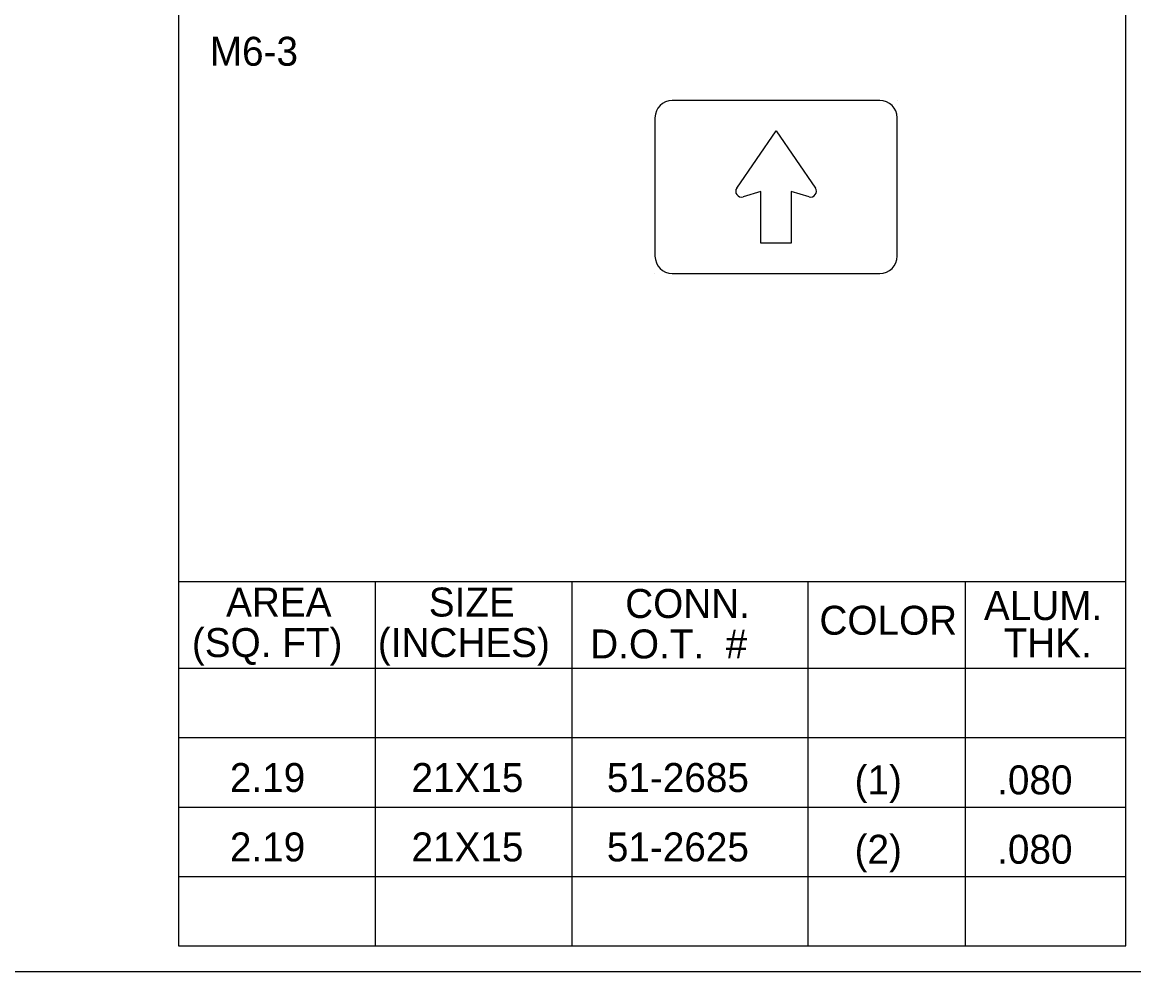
# Model space of a CAD drawing. Extents: x 0 to 2011, y -22 to 1183.
# Drawn here: x 616.3 to 739.2, y 59 to 163.9 of the extents above; entities that cross this region are included whole.
import ezdxf

# ---------------------------------------------------------------- set-up
doc = ezdxf.new("R2010")
doc.units = 0
for name, color, linetype in [('CT_Construction', 7, 'Continuous'), ('Level 1', 7, 'Continuous'), ('Level 2', 7, 'Continuous'), ('Level 5', 7, 'Continuous')]:
    doc.layers.add(name, color=color, linetype=linetype)

msp = doc.modelspace()

# ---------------------------------------------------------------- linework, layer by layer
at = {"layer": 'CT_Construction'}
msp.add_lwpolyline([(0, 829.03), (1270, 829.03), (1270, 59.03), (0, 59.03)], close=True, dxfattribs=at)
at = {"layer": 'Level 1'}
for p, q in [((711.09, 155.31), (688.14, 155.31)), ((686.23, 153.4), (686.23, 138.1)), ((713, 138.1), (713, 153.4)), ((695.27, 145.63), (699.62, 151.96)), ((699.62, 151.96), (699.62, 151.96)), ((699.62, 151.96), (699.62, 151.96)), ((699.62, 151.96), (703.97, 145.63)), ((697.94, 145.25), (695.98, 144.66)), ((697.94, 139.53), (697.94, 145.25)), ((703.26, 144.66), (701.29, 145.25)), ((701.29, 145.25), (701.29, 139.53)), ((701.29, 139.53), (697.94, 139.53)), ((688.14, 136.19), (711.09, 136.19))]:
    msp.add_line(p, q, dxfattribs=at)
for centre, radius, start, end in [((688.14, 153.4), 1.91, 90, 180), ((711.09, 153.4), 1.91, 0, 90), ((695.79, 145.27), 0.637, 145.5114, 286.6409), ((703.44, 145.27), 0.637, 253.3591, 34.4886), ((688.14, 138.1), 1.91, 180, 270), ((711.09, 138.1), 1.91, 270, 360)]:
    msp.add_arc(centre, radius, start, end, dxfattribs=at)
at = {"layer": 'Level 2'}
for p, q in [((713, 155.31), (713, 155.31)), ((699.62, 139.53), (699.62, 139.53)), ((686.23, 136.19), (686.23, 136.19)), ((633.54, 102.16), (738.29, 102.16)), ((655.29, 102.16), (655.29, 61.88)), ((677.04, 102.16), (677.04, 61.88)), ((703.14, 102.16), (703.14, 61.88)), ((720.54, 102.16), (720.54, 61.88)), ((633.54, 92.57), (738.29, 92.57)), ((633.54, 84.9), (738.29, 84.9)), ((633.54, 77.22), (738.29, 77.22)), ((633.54, 69.55), (738.29, 69.55))]:
    msp.add_line(p, q, dxfattribs=at)
msp.add_lwpolyline([(738.29, 165.5), (633.54, 165.5), (633.54, 61.88), (738.29, 61.88)], close=True, dxfattribs=at)
msp.add_lwpolyline([(701.25, 139.53), (701.29, 139.58)], dxfattribs=at)
at = {"layer": 'Level 5'}
msp.add_line((633.54, 391.26), (633.54, 61.88), dxfattribs=at)

# ---------------------------------------------------------------- texts
at = {"layer": 'Level 2'}
for s, p in [('M6-3', (637.01, 159.14)), ('AREA', (638.81, 98.28)), ('SIZE', (661.22, 98.28)), ('CONN.', (682.94, 98.12)), ('ALUM.', (722.6, 97.89)), ('COLOR', (704.41, 96.27)), ('(SQ. FT)', (635.03, 93.8)), ('(INCHES)', (655.59, 93.8)), ('D.O.T.  #', (679.07, 93.65)), ('THK.', (724.78, 93.76))]:
    msp.add_text(s, height=3.2, dxfattribs=at).set_placement(p)
at = {"layer": 'Level 5'}
for s, p in [(' 2.19', (638.04, 78.89)), ('21X15', (659.31, 78.89)), ('51-2685', (680.91, 78.89)), ('(1)', (708.3, 78.63)), ('.080', (724.06, 78.63)), (' 2.19', (638.04, 71.22)), ('21X15', (659.31, 71.22)), ('51-2625', (680.91, 71.22)), ('(2)', (708.3, 70.96)), ('.080', (724.06, 70.96))]:
    msp.add_text(s, height=3.2, dxfattribs=at).set_placement(p)

doc.saveas('drawing.dxf')
